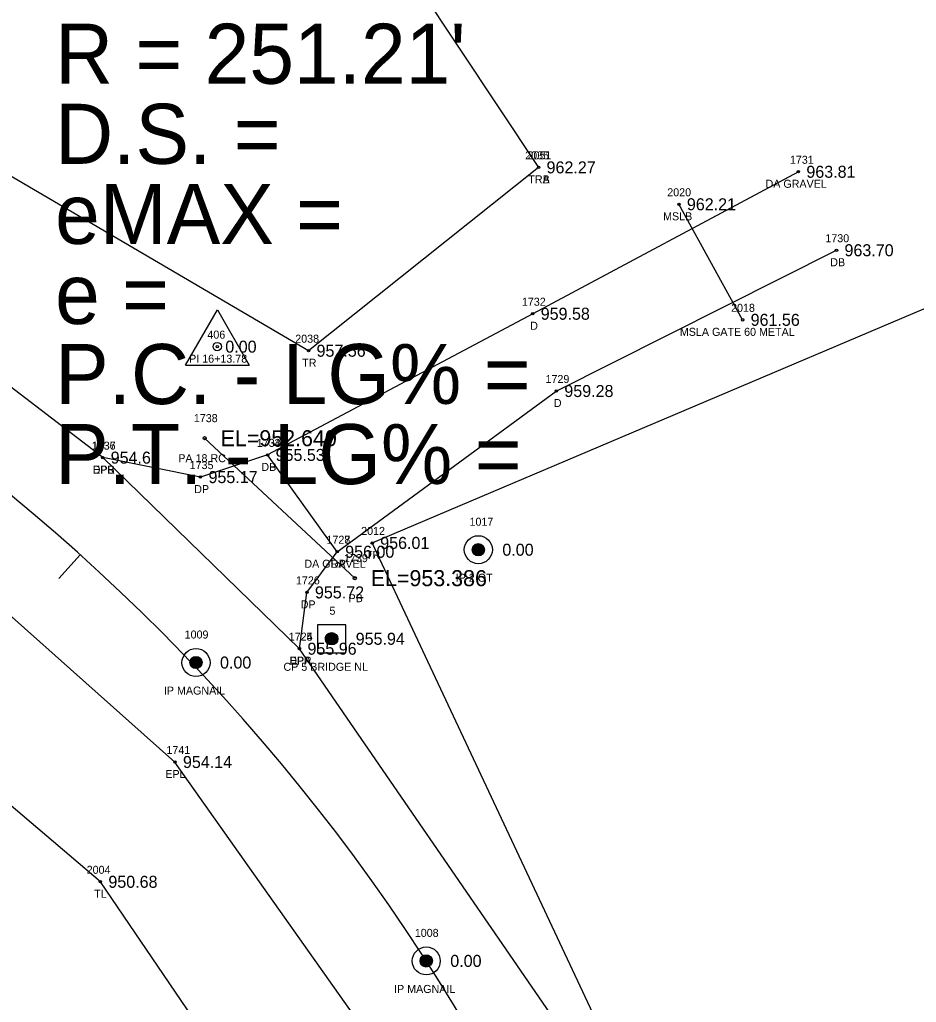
# Model space of a CAD drawing. Extents: x 1528109 to 1531398, y 1157799 to 1162548.
# Drawn here: x 1530489.6 to 1530601.5, y 1159018.3 to 1159141 of the extents above; entities that cross this region are included whole.
import ezdxf

# ---------------------------------------------------------------- set-up
doc = ezdxf.new("R2010")
doc.units = 0
for name, color, linetype in [('RD_EX_DR_Pipe', 7, 'Continuous'), ('RD_EX_DR_Pipe_txCode', 7, 'Continuous'), ('RD_EX_Driveway', 7, 'Continuous'), ('RD_EX_Driveway_txCode', 7, 'Continuous'), ('RD_EX_DV_Prop_txCode', 7, 'Continuous'), ('RD_EX_DV_PropPin', 7, 'Continuous'), ('RD_EX_Misc', 7, 'Continuous'), ('RD_EX_Misc_txCode', 7, 'Continuous'), ('RD_EX_Road', 7, 'Continuous'), ('RD_EX_Road_txCode', 7, 'Continuous'), ('RD_EX_TX_Driveway_ELEV', 7, 'Continuous'), ('RD_EX_TX_DV_Prop_ELEV', 7, 'Continuous'), ('RD_EX_TX_Misc_ELEV', 7, 'Continuous'), ('RD_EX_TX_Road_ELEV', 7, 'Continuous'), ('RD_EX_TX_VEG_ELEV', 7, 'Continuous'), ('RD_EX_VEG', 7, 'Continuous'), ('RD_EX_VEG_txCode', 7, 'Continuous'), ('RD_HC_Cl', 7, 'Continuous'), ('RD_HC_Data', 7, 'Continuous'), ('RD_HC_Data_Tic', 7, 'Continuous'), ('RD_HC_Survey', 7, 'Continuous'), ('RD_HC_Survey_ELEV', 7, 'Continuous'), ('RD_HC_Survey_txCode', 7, 'Continuous'), ('RD_HC_txCode', 7, 'Continuous'), ('RD_SMD_Locator', 7, 'Continuous'), ('RD_TX_Pipe_ElevEX', 7, 'Continuous')]:
    doc.layers.add(name, color=color, linetype=linetype)

msp = doc.modelspace()

# ---------------------------------------------------------------- linework, layer by layer
at = {"layer": 'RD_EX_DR_Pipe'}
msp.add_line((1530512.67, 1159088.74), (1530531.41, 1159071.26), dxfattribs=at)
at = {"layer": 'RD_EX_Driveway'}
for points in [[(1530586.8, 1159122.01), (1530553.63, 1159104.28), (1530520.53, 1159086.65)], [(1530529.22, 1159074.56), (1530556.58, 1159094.63), (1530591.56, 1159112.21)], [(1530524.51, 1159062.45), (1530525.44, 1159069.48), (1530529.22, 1159074.56), (1530520.53, 1159086.65), (1530512.15, 1159083.88), (1530499.94, 1159086.31)]]:
    msp.add_lwpolyline(points, dxfattribs=at)
at = {"layer": 'RD_EX_DV_PropPin'}
for p, q in [((1530546.56, 1159074.11), (1530546.56, 1159075.52)), ((1530546.6, 1159074.09), (1530546.6, 1159075.53)), ((1530546.63, 1159074.08), (1530546.63, 1159075.54)), ((1530546.67, 1159074.07), (1530546.67, 1159075.55)), ((1530546.7, 1159074.07), (1530546.7, 1159075.56)), ((1530546.74, 1159074.06), (1530546.74, 1159075.57)), ((1530546.77, 1159074.06), (1530546.77, 1159075.57)), ((1530546.81, 1159074.05), (1530546.81, 1159075.57)), ((1530546.84, 1159074.05), (1530546.84, 1159075.57)), ((1530546.88, 1159074.05), (1530546.88, 1159075.57)), ((1530546.91, 1159074.06), (1530546.91, 1159075.57)), ((1530546.95, 1159074.06), (1530546.95, 1159075.57)), ((1530546.98, 1159074.07), (1530546.98, 1159075.56)), ((1530547.02, 1159074.07), (1530547.02, 1159075.55)), ((1530547.05, 1159074.08), (1530547.05, 1159075.54)), ((1530547.09, 1159074.09), (1530547.09, 1159075.53)), ((1530547.12, 1159074.11), (1530547.12, 1159075.52)), ((1530546.11, 1159074.62), (1530546.11, 1159075.01)), ((1530546.14, 1159074.52), (1530546.14, 1159075.11)), ((1530546.18, 1159074.44), (1530546.18, 1159075.18)), ((1530546.21, 1159074.39), (1530546.21, 1159075.24)), ((1530546.25, 1159074.34), (1530546.25, 1159075.29)), ((1530546.28, 1159074.3), (1530546.28, 1159075.33)), ((1530546.32, 1159074.26), (1530546.32, 1159075.36)), ((1530546.35, 1159074.23), (1530546.35, 1159075.4)), ((1530546.39, 1159074.2), (1530546.39, 1159075.42)), ((1530546.42, 1159074.18), (1530546.42, 1159075.45)), ((1530546.46, 1159074.16), (1530546.46, 1159075.47)), ((1530546.49, 1159074.14), (1530546.49, 1159075.49)), ((1530546.53, 1159074.12), (1530546.53, 1159075.51)), ((1530547.16, 1159074.12), (1530547.16, 1159075.51)), ((1530547.19, 1159074.14), (1530547.19, 1159075.49)), ((1530547.23, 1159074.16), (1530547.23, 1159075.47)), ((1530547.26, 1159074.18), (1530547.26, 1159075.45)), ((1530547.3, 1159074.2), (1530547.3, 1159075.42)), ((1530547.33, 1159074.23), (1530547.33, 1159075.4)), ((1530547.37, 1159074.26), (1530547.37, 1159075.36)), ((1530547.4, 1159074.3), (1530547.4, 1159075.33)), ((1530547.44, 1159074.34), (1530547.44, 1159075.29)), ((1530547.47, 1159074.39), (1530547.47, 1159075.24)), ((1530547.51, 1159074.44), (1530547.51, 1159075.18)), ((1530547.54, 1159074.52), (1530547.54, 1159075.11)), ((1530547.58, 1159074.62), (1530547.58, 1159075.01)), ((1530510.86, 1159060.52), (1530510.86, 1159060.92)), ((1530510.89, 1159060.42), (1530510.89, 1159061.02)), ((1530510.93, 1159060.35), (1530510.93, 1159061.09)), ((1530510.96, 1159060.29), (1530510.96, 1159061.15)), ((1530511, 1159060.25), (1530511, 1159061.19)), ((1530511.03, 1159060.21), (1530511.03, 1159061.24)), ((1530511.07, 1159060.17), (1530511.07, 1159061.27)), ((1530511.1, 1159060.14), (1530511.1, 1159061.3)), ((1530511.14, 1159060.11), (1530511.14, 1159061.33)), ((1530511.17, 1159060.09), (1530511.17, 1159061.35)), ((1530511.21, 1159060.06), (1530511.21, 1159061.38)), ((1530511.24, 1159060.04), (1530511.24, 1159061.4)), ((1530511.28, 1159060.03), (1530511.28, 1159061.41)), ((1530511.31, 1159060.01), (1530511.31, 1159061.43)), ((1530511.35, 1159060), (1530511.35, 1159061.44)), ((1530511.38, 1159059.99), (1530511.38, 1159061.45)), ((1530511.42, 1159059.98), (1530511.42, 1159061.46)), ((1530511.45, 1159059.97), (1530511.45, 1159061.47)), ((1530511.49, 1159059.97), (1530511.49, 1159061.47)), ((1530511.52, 1159059.96), (1530511.52, 1159061.48)), ((1530511.56, 1159059.96), (1530511.56, 1159061.48)), ((1530511.59, 1159059.96), (1530511.59, 1159061.48)), ((1530511.63, 1159059.96), (1530511.63, 1159061.48)), ((1530511.66, 1159059.96), (1530511.66, 1159061.48)), ((1530511.7, 1159059.97), (1530511.7, 1159061.47)), ((1530511.73, 1159059.97), (1530511.73, 1159061.47)), ((1530511.77, 1159059.98), (1530511.77, 1159061.46)), ((1530511.8, 1159059.99), (1530511.8, 1159061.45)), ((1530511.84, 1159060), (1530511.84, 1159061.44)), ((1530511.87, 1159060.01), (1530511.87, 1159061.43)), ((1530511.91, 1159060.03), (1530511.91, 1159061.41)), ((1530511.94, 1159060.04), (1530511.94, 1159061.4)), ((1530511.98, 1159060.06), (1530511.98, 1159061.38)), ((1530512.01, 1159060.09), (1530512.01, 1159061.35)), ((1530512.05, 1159060.11), (1530512.05, 1159061.33)), ((1530512.08, 1159060.14), (1530512.08, 1159061.3)), ((1530512.12, 1159060.17), (1530512.12, 1159061.27)), ((1530512.15, 1159060.21), (1530512.15, 1159061.24)), ((1530512.19, 1159060.25), (1530512.19, 1159061.19)), ((1530512.22, 1159060.29), (1530512.22, 1159061.15)), ((1530512.26, 1159060.35), (1530512.26, 1159061.09)), ((1530512.29, 1159060.42), (1530512.29, 1159061.02)), ((1530512.33, 1159060.52), (1530512.33, 1159060.92)), ((1530539.78, 1159022.94), (1530539.78, 1159023.97)), ((1530539.81, 1159022.91), (1530539.81, 1159024.01)), ((1530539.85, 1159022.88), (1530539.85, 1159024.04)), ((1530539.88, 1159022.85), (1530539.88, 1159024.07)), ((1530539.92, 1159022.82), (1530539.92, 1159024.09)), ((1530539.95, 1159022.8), (1530539.95, 1159024.11)), ((1530539.99, 1159022.78), (1530539.99, 1159024.13)), ((1530540.02, 1159022.76), (1530540.02, 1159024.15)), ((1530540.06, 1159022.75), (1530540.06, 1159024.17)), ((1530540.09, 1159022.74), (1530540.09, 1159024.18)), ((1530540.13, 1159022.73), (1530540.13, 1159024.19)), ((1530540.16, 1159022.72), (1530540.16, 1159024.2)), ((1530540.2, 1159022.71), (1530540.2, 1159024.21)), ((1530540.23, 1159022.7), (1530540.23, 1159024.21)), ((1530540.27, 1159022.7), (1530540.27, 1159024.22)), ((1530540.3, 1159022.7), (1530540.3, 1159024.22)), ((1530540.34, 1159022.7), (1530540.34, 1159024.22)), ((1530540.37, 1159022.7), (1530540.37, 1159024.22)), ((1530540.41, 1159022.7), (1530540.41, 1159024.22)), ((1530540.44, 1159022.7), (1530540.44, 1159024.21)), ((1530540.48, 1159022.71), (1530540.48, 1159024.21)), ((1530540.51, 1159022.72), (1530540.51, 1159024.2)), ((1530540.55, 1159022.73), (1530540.55, 1159024.19)), ((1530540.58, 1159022.74), (1530540.58, 1159024.18)), ((1530540.62, 1159022.75), (1530540.62, 1159024.17)), ((1530540.65, 1159022.76), (1530540.65, 1159024.15)), ((1530540.69, 1159022.78), (1530540.69, 1159024.13)), ((1530540.72, 1159022.8), (1530540.72, 1159024.11)), ((1530540.76, 1159022.82), (1530540.76, 1159024.09)), ((1530540.79, 1159022.85), (1530540.79, 1159024.07)), ((1530540.83, 1159022.88), (1530540.83, 1159024.04)), ((1530540.86, 1159022.91), (1530540.86, 1159024.01)), ((1530540.9, 1159022.94), (1530540.9, 1159023.97)), ((1530539.6, 1159023.26), (1530539.6, 1159023.65)), ((1530539.64, 1159023.16), (1530539.64, 1159023.76)), ((1530539.67, 1159023.09), (1530539.67, 1159023.83)), ((1530539.71, 1159023.03), (1530539.71, 1159023.88)), ((1530539.74, 1159022.98), (1530539.74, 1159023.93)), ((1530540.93, 1159022.98), (1530540.93, 1159023.93)), ((1530540.97, 1159023.03), (1530540.97, 1159023.88)), ((1530541, 1159023.09), (1530541, 1159023.83)), ((1530541.04, 1159023.16), (1530541.04, 1159023.76)), ((1530541.07, 1159023.26), (1530541.07, 1159023.65))]:
    msp.add_line(p, q, dxfattribs=at)
for centre, radius in [((1530546.84, 1159074.81), 1.75), ((1530546.84, 1159074.81), 0.761), ((1530511.59, 1159060.72), 1.75), ((1530511.59, 1159060.72), 0.761), ((1530540.34, 1159023.46), 1.75), ((1530540.34, 1159023.46), 0.761)]:
    msp.add_circle(centre, radius, dxfattribs=at)
at = {"layer": 'RD_EX_Misc'}
msp.add_line((1530579.84, 1159103.52), (1530571.88, 1159117.95), dxfattribs=at)
at = {"layer": 'RD_EX_Road'}
for points in [[(1530704.87, 1158597.47), (1530691.01, 1158649.88), (1530681.22, 1158687.32), (1530670.59, 1158725), (1530654.42, 1158774.07), (1530635.35, 1158823.15), (1530627.8, 1158842.3), (1530617.35, 1158868.69), (1530597.91, 1158918.04), (1530578.53, 1158967.57), (1530556.7, 1159015.66), (1530524.51, 1159062.45), (1530499.94, 1159086.31), (1530481.93, 1159100.12), (1530434.53, 1159127), (1530416.95, 1159134.13), (1530380.01, 1159145.61), (1530337.52, 1159156.44)], [(1530685.41, 1158592.23), (1530678.87, 1158616.46), (1530671.67, 1158642.17), (1530661.52, 1158682.33), (1530651.17, 1158718.79), (1530644.65, 1158739.35), (1530638.95, 1158757.58), (1530635.45, 1158767.4), (1530616.88, 1158814.94), (1530597.61, 1158862.78), (1530579.09, 1158910.21), (1530559.73, 1158959.38), (1530538.76, 1159006.16), (1530508.96, 1159048.3), (1530469.44, 1159083.44), (1530424.03, 1159108.51), (1530374.97, 1159125.76), (1530332.28, 1159136.67)]]:
    msp.add_lwpolyline(points, dxfattribs=at)
at = {"layer": 'RD_EX_VEG'}
for points in [[(1530554.36, 1159122.56), (1530525.64, 1159099.66), (1530455.01, 1159141.08), (1530491.77, 1159185.08), (1530529.52, 1159159.95), (1530554.36, 1159122.56)], [(1530558.31, 1158802.21), (1530584.73, 1158806.6), (1530608.93, 1158749.85), (1530624.81, 1158756.88), (1530598.74, 1158838.75), (1530544.19, 1158967.8), (1530499.65, 1159033.34), (1530444.6, 1159080.15), (1530373.76, 1159115.62), (1530558.31, 1158802.21)], [(1530670.99, 1158924.86), (1530623.24, 1158884.55), (1530533.59, 1159075.66), (1530606.57, 1159106.64)]]:
    msp.add_lwpolyline(points, dxfattribs=at)
at = {"layer": 'RD_HC_Cl'}
msp.add_arc((1530329.18, 1158887.37), 251.21, 21.955, 76.0174, dxfattribs=at)
at = {"layer": 'RD_HC_Data'}
for p, q in [((1530510.28, 1159097.87), (1530514.26, 1159104.75)), ((1530514.26, 1159104.75), (1530518.22, 1159097.87)), ((1530510.28, 1159097.87), (1530518.22, 1159097.87))]:
    msp.add_line(p, q, dxfattribs=at)
msp.add_circle((1530514.25, 1159100.17), 0.529, dxfattribs=at)
at = {"layer": 'RD_HC_Data_Tic'}
msp.add_line((1530497.13, 1159074.19), (1530494.45, 1159071.21), dxfattribs=at)
at = {"layer": 'RD_HC_Survey'}
for p, q in [((1530528.52, 1159062.92), (1530528.52, 1159064.46)), ((1530528.55, 1159062.92), (1530528.55, 1159064.46)), ((1530527.78, 1159063.51), (1530527.78, 1159063.87)), ((1530527.81, 1159063.43), (1530527.81, 1159063.96)), ((1530527.83, 1159063.37), (1530527.83, 1159064.02)), ((1530527.86, 1159063.32), (1530527.86, 1159064.06)), ((1530527.88, 1159063.28), (1530527.88, 1159064.11)), ((1530527.91, 1159063.24), (1530527.91, 1159064.14)), ((1530527.93, 1159063.21), (1530527.93, 1159064.18)), ((1530527.96, 1159063.18), (1530527.96, 1159064.21)), ((1530527.98, 1159063.16), (1530527.98, 1159064.23)), ((1530528.01, 1159063.13), (1530528.01, 1159064.26)), ((1530528.03, 1159063.11), (1530528.03, 1159064.28)), ((1530528.05, 1159063.09), (1530528.05, 1159064.3)), ((1530528.08, 1159063.07), (1530528.08, 1159064.32)), ((1530528.1, 1159063.05), (1530528.1, 1159064.33)), ((1530528.13, 1159063.04), (1530528.13, 1159064.35)), ((1530528.15, 1159063.02), (1530528.15, 1159064.36)), ((1530528.18, 1159063.01), (1530528.18, 1159064.38)), ((1530528.2, 1159063), (1530528.2, 1159064.39)), ((1530528.23, 1159062.99), (1530528.23, 1159064.4)), ((1530528.25, 1159062.98), (1530528.25, 1159064.41)), ((1530528.28, 1159062.97), (1530528.28, 1159064.42)), ((1530528.3, 1159062.96), (1530528.3, 1159064.43)), ((1530528.33, 1159062.95), (1530528.33, 1159064.44)), ((1530528.35, 1159062.95), (1530528.35, 1159064.44)), ((1530528.38, 1159062.94), (1530528.38, 1159064.45)), ((1530528.4, 1159062.94), (1530528.4, 1159064.45)), ((1530528.43, 1159062.93), (1530528.43, 1159064.46)), ((1530528.45, 1159062.93), (1530528.45, 1159064.46)), ((1530528.48, 1159062.93), (1530528.48, 1159064.46)), ((1530528.5, 1159062.92), (1530528.5, 1159064.46)), ((1530528.57, 1159062.93), (1530528.57, 1159064.46)), ((1530528.6, 1159062.93), (1530528.6, 1159064.46)), ((1530528.62, 1159062.93), (1530528.62, 1159064.46)), ((1530528.65, 1159062.93), (1530528.65, 1159064.45)), ((1530528.67, 1159062.94), (1530528.67, 1159064.45)), ((1530528.7, 1159062.94), (1530528.7, 1159064.44)), ((1530528.72, 1159062.95), (1530528.72, 1159064.44)), ((1530528.75, 1159062.96), (1530528.75, 1159064.43)), ((1530528.77, 1159062.96), (1530528.77, 1159064.42)), ((1530528.8, 1159062.97), (1530528.8, 1159064.42)), ((1530528.82, 1159062.98), (1530528.82, 1159064.41)), ((1530528.85, 1159062.99), (1530528.85, 1159064.4)), ((1530528.87, 1159063), (1530528.87, 1159064.38)), ((1530528.9, 1159063.02), (1530528.9, 1159064.37)), ((1530528.92, 1159063.03), (1530528.92, 1159064.36)), ((1530528.95, 1159063.05), (1530528.95, 1159064.34)), ((1530528.97, 1159063.06), (1530528.97, 1159064.33)), ((1530529, 1159063.08), (1530529, 1159064.31)), ((1530529.02, 1159063.1), (1530529.02, 1159064.29)), ((1530529.04, 1159063.12), (1530529.04, 1159064.27)), ((1530529.07, 1159063.14), (1530529.07, 1159064.24)), ((1530529.09, 1159063.17), (1530529.09, 1159064.22)), ((1530529.12, 1159063.2), (1530529.12, 1159064.19)), ((1530529.14, 1159063.23), (1530529.14, 1159064.16)), ((1530529.17, 1159063.26), (1530529.17, 1159064.12)), ((1530529.19, 1159063.3), (1530529.19, 1159064.09)), ((1530529.22, 1159063.35), (1530529.22, 1159064.04)), ((1530529.24, 1159063.4), (1530529.24, 1159063.99)), ((1530529.27, 1159063.47), (1530529.27, 1159063.92)), ((1530529.29, 1159063.58), (1530529.29, 1159063.81))]:
    msp.add_line(p, q, dxfattribs=at)
msp.add_lwpolyline([(1530530.28, 1159065.44), (1530526.78, 1159065.44), (1530526.78, 1159061.94), (1530530.28, 1159061.94)], close=True, dxfattribs=at)
msp.add_circle((1530528.53, 1159063.69), 0.769, dxfattribs=at)
at = {"layer": 'RD_SMD_Locator'}
for centre, radius in [((1530554.36, 1159122.56), 0.15), ((1530554.36, 1159122.56), 0.15), ((1530586.8, 1159122.01), 0.15), ((1530571.88, 1159117.95), 0.15), ((1530591.56, 1159112.21), 0.15), ((1530553.63, 1159104.28), 0.15), ((1530579.84, 1159103.52), 0.15), ((1530514.25, 1159100.17), 0.15), ((1530525.64, 1159099.66), 0.15), ((1530556.58, 1159094.63), 0.15), ((1530512.67, 1159088.74), 0.2), ((1530520.53, 1159086.65), 0.15), ((1530520.53, 1159086.65), 0.15), ((1530499.94, 1159086.31), 0.15), ((1530499.94, 1159086.31), 0.15), ((1530512.15, 1159083.88), 0.15), ((1530533.59, 1159075.66), 0.15), ((1530529.22, 1159074.56), 0.15), ((1530529.22, 1159074.56), 0.15), ((1530546.84, 1159074.81), 0.15), ((1530531.41, 1159071.26), 0.2), ((1530525.44, 1159069.48), 0.15), ((1530528.53, 1159063.69), 0.15), ((1530524.51, 1159062.45), 0.15), ((1530524.51, 1159062.45), 0.15), ((1530511.59, 1159060.72), 0.15), ((1530508.96, 1159048.3), 0.15), ((1530499.65, 1159033.34), 0.15), ((1530540.34, 1159023.46), 0.15)]:
    msp.add_circle(centre, radius, dxfattribs=at)

# ---------------------------------------------------------------- texts
at = {"layer": 'RD_EX_DR_Pipe_txCode'}
for s, p in [('1738', (1530511.32, 1159090.74)), ('PA 18 RC', (1530509.38, 1159085.74)), ('1739', (1530530.07, 1159073.26)), ('PB', (1530530.63, 1159068.26))]:
    msp.add_text(s, height=1, dxfattribs=at).set_placement(p)
at = {"layer": 'RD_EX_Driveway_txCode'}
for s, p in [('1731', (1530585.74, 1159123.01)), ('DA GRAVEL', (1530582.7, 1159120.01)), ('1730', (1530590.17, 1159113.21)), ('DB', (1530590.78, 1159110.21)), ('1732', (1530552.28, 1159105.28)), ('D', (1530553.32, 1159102.28)), ('1729', (1530555.23, 1159095.63)), ('D', (1530556.27, 1159092.63)), ('1736', (1530498.57, 1159087.31)), ('1733', (1530519.18, 1159087.65)), ('1734', (1530519.18, 1159087.65)), ('1735', (1530510.8, 1159084.88)), ('DB', (1530519.75, 1159084.65)), ('DP', (1530519.75, 1159084.65)), ('DPB', (1530498.69, 1159084.31)), ('DP', (1530511.37, 1159081.88)), ('1727', (1530527.88, 1159075.56)), ('1728', (1530527.88, 1159075.56)), ('DA GRAVEL', (1530525.12, 1159072.56)), ('DP', (1530528.44, 1159072.56)), ('1726', (1530524.07, 1159070.48)), ('DP', (1530524.66, 1159067.48)), ('1725', (1530523.17, 1159063.45)), ('DPA', (1530523.24, 1159060.45))]:
    msp.add_text(s, height=1, dxfattribs=at).set_placement(p)
at = {"layer": 'RD_EX_DV_Prop_txCode'}
for s, p in [('1017', (1530545.74, 1159077.81)), ('IP 2 OT', (1530544.02, 1159070.81)), ('1009', (1530510.17, 1159063.72)), ('IP MAGNAIL', (1530507.58, 1159056.72)), ('1008', (1530538.91, 1159026.46)), ('IP MAGNAIL', (1530536.32, 1159019.46))]:
    msp.add_text(s, height=1, dxfattribs=at).set_placement(p)
at = {"layer": 'RD_EX_Misc_txCode'}
for s, p in [('2020', (1530570.43, 1159118.95)), ('MSLB', (1530569.91, 1159115.95)), ('2018', (1530578.4, 1159104.52)), ('MSLA GATE 60 METAL', (1530572, 1159101.52))]:
    msp.add_text(s, height=1, dxfattribs=at).set_placement(p)
at = {"layer": 'RD_EX_Road_txCode'}
for s, p in [('1737', (1530498.59, 1159087.31)), ('EPR', (1530498.71, 1159084.31)), ('1724', (1530523.17, 1159063.45)), ('EPR', (1530523.28, 1159060.45)), ('1741', (1530507.9, 1159049.3)), ('EPL', (1530507.76, 1159046.3))]:
    msp.add_text(s, height=1, dxfattribs=at).set_placement(p)
at = {"layer": 'RD_EX_TX_Driveway_ELEV'}
for s, p in [('963.81', (1530587.8, 1159121.26)), ('963.70', (1530592.56, 1159111.46)), ('959.58', (1530554.63, 1159103.53)), ('959.28', (1530557.58, 1159093.88)), ('954.63', (1530500.94, 1159085.56)), ('955.53', (1530521.53, 1159085.9)), ('955.53', (1530521.53, 1159085.9)), ('955.17', (1530513.15, 1159083.13)), ('956.00', (1530530.22, 1159073.81)), ('956.00', (1530530.22, 1159073.81)), ('955.72', (1530526.44, 1159068.73)), ('955.96', (1530525.51, 1159061.7))]:
    msp.add_text(s, height=1.5, dxfattribs=at).set_placement(p)
at = {"layer": 'RD_EX_TX_DV_Prop_ELEV'}
for p in [(1530549.84, 1159074.06), (1530514.59, 1159059.97), (1530543.34, 1159022.71)]:
    msp.add_text('0.00', height=1.5, dxfattribs=at).set_placement(p)
at = {"layer": 'RD_EX_TX_Misc_ELEV'}
for s, p in [('962.21', (1530572.88, 1159117.2)), ('961.56', (1530580.84, 1159102.77))]:
    msp.add_text(s, height=1.5, dxfattribs=at).set_placement(p)
at = {"layer": 'RD_EX_TX_Road_ELEV'}
for s, p in [('954.63', (1530500.94, 1159085.56)), ('955.96', (1530525.51, 1159061.7)), ('954.14', (1530509.96, 1159047.55))]:
    msp.add_text(s, height=1.5, dxfattribs=at).set_placement(p)
at = {"layer": 'RD_EX_TX_VEG_ELEV'}
for s, p in [('962.27', (1530555.36, 1159121.81)), ('962.27', (1530555.36, 1159121.81)), ('957.56', (1530526.64, 1159098.91)), ('956.01', (1530534.59, 1159074.91)), ('950.68', (1530500.65, 1159032.59))]:
    msp.add_text(s, height=1.5, dxfattribs=at).set_placement(p)
at = {"layer": 'RD_EX_VEG_txCode'}
for s, p in [('2035', (1530552.69, 1159123.56)), ('2051', (1530552.98, 1159123.56)), ('TRA', (1530553.08, 1159120.56)), ('TRB', (1530553.09, 1159120.56)), ('2038', (1530523.98, 1159100.66)), ('TR', (1530524.85, 1159097.66)), ('2012', (1530532.21, 1159076.66)), ('TR', (1530532.8, 1159073.66)), ('2004', (1530497.94, 1159034.34)), ('TL', (1530498.88, 1159031.34))]:
    msp.add_text(s, height=1, dxfattribs=at).set_placement(p)
at = {"layer": 'RD_HC_Data'}
for s, p in [("R = 251.21'", (1530494, 1159133)), ('D.S. = ', (1530494, 1159123)), ('eMAX = ', (1530494, 1159113)), ('e = ', (1530494, 1159103)), ('P.C. - LG% = ', (1530494, 1159093)), ('P.T. - LG% = ', (1530494, 1159083))]:
    msp.add_text(s, height=7.5, dxfattribs=at).set_placement(p)
at = {"layer": 'RD_HC_Survey_ELEV'}
for s, p in [('0.00', (1530515.25, 1159099.42)), ('955.94', (1530531.53, 1159062.94))]:
    msp.add_text(s, height=1.5, dxfattribs=at).set_placement(p)
at = {"layer": 'RD_HC_Survey_txCode'}
for s, p in [('5', (1530528.25, 1159066.69)), ('CP 5 BRIDGE NL', (1530522.51, 1159059.69))]:
    msp.add_text(s, height=1, dxfattribs=at).set_placement(p)
at = {"layer": 'RD_HC_txCode'}
for s, p in [('406', (1530513.01, 1159101.17)), ('PI 16+13.78', (1530510.73, 1159098.17))]:
    msp.add_text(s, height=1, dxfattribs=at).set_placement(p)
at = {"layer": 'RD_TX_Pipe_ElevEX'}
for s, p in [('EL=952.640', (1530514.67, 1159087.74)), ('EL=953.386', (1530533.41, 1159070.26))]:
    msp.add_text(s, height=2, dxfattribs=at).set_placement(p)

doc.saveas('drawing.dxf')
